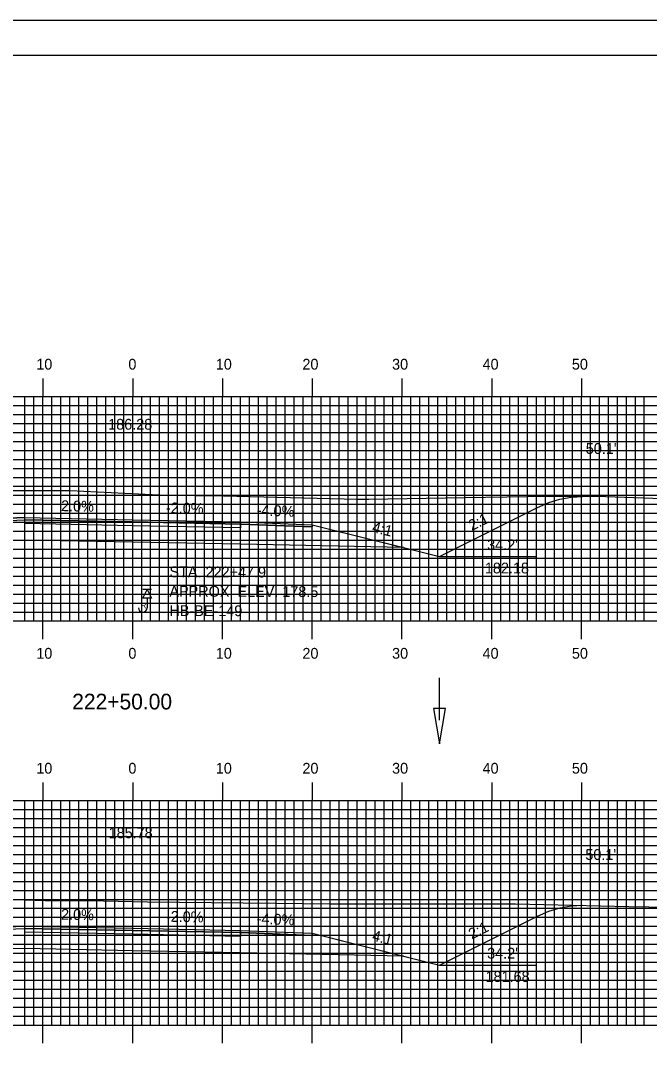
# Model space of a CAD drawing. Extents: x 1797601 to 1797944, y 442591 to 442811.
# Drawn here: x 1797753.9 to 1797824, y 442696.2 to 442810.5 of the extents above; entities that cross this region are included whole.
import ezdxf

# ---------------------------------------------------------------- set-up
doc = ezdxf.new("R2010")
doc.units = 0
for name, color, linetype in [('ANNOTATION', 7, 'Continuous'), ('BORDER', 7, 'Continuous'), ('BORING - REFUSAL', 7, 'Continuous'), ('D_Drainage_Ditch_Line', 7, 'Continuous'), ('D_Roadway_Centerline', 7, 'Continuous'), ('D_Roadway_Centerline_Text', 7, 'Continuous'), ('D_Roadway_Edge_Shoulder', 7, 'Continuous'), ('D_Roadway_Edge_TW', 7, 'Continuous'), ('D_Roadway_Pavement', 7, 'Continuous'), ('D_Roadway_SlopeLines', 7, 'Continuous'), ('D_Roadway_SubGrade', 7, 'Continuous'), ('D_Text_Standard', 7, 'Continuous'), ('H_V ANNOTATION', 7, 'Continuous'), ('MAJOR', 7, 'Continuous'), ('MINOR', 7, 'Continuous'), ('PDRAIN', 7, 'Continuous'), ('PLOT BOUNDARY', 7, 'Continuous'), ('S_Roadway_Centerline', 7, 'Continuous')]:
    doc.layers.add(name, color=color, linetype=linetype)

msp = doc.modelspace()

# ---------------------------------------------------------------- linework, layer by layer
at = {"layer": 'BORDER'}
msp.add_lwpolyline([(1797616.84, 442596.67), (1797936.84, 442596.67), (1797936.84, 442806.67), (1797616.84, 442806.67)], close=True, dxfattribs=at)
at = {"layer": 'BORING - REFUSAL'}
for p, q in [((1797768.52, 442747.17), (1797767.56, 442747.17)), ((1797768.04, 442746.21), (1797768.04, 442745.15))]:
    msp.add_line(p, q, dxfattribs=at)
msp.add_lwpolyline([(1797768.04, 442747.17), (1797768.52, 442746.21), (1797767.56, 442746.21)], close=True, dxfattribs=at)
msp.add_arc((1797767.56, 442745.15), 0.485, 180, 0, dxfattribs=at)
at = {"layer": 'D_Drainage_Ditch_Line'}
msp.add_line((1797800.62, 442732.63), (1797800.62, 442737.33), dxfattribs=at)
msp.add_lwpolyline([(1797801.28, 442733.94), (1797799.96, 442733.94), (1797800.62, 442730)], close=True, dxfattribs=at)
at = {"layer": 'D_Roadway_Centerline'}
for points in [[(1797715.7, 442758.42), (1797716.95, 442758.32), (1797718.2, 442758.06), (1797719.45, 442757.66), (1797720.7, 442757.11), (1797732.27, 442751.33), (1797736.27, 442752.33), (1797746.44, 442754.87), (1797754.44, 442755.19), (1797766.44, 442754.95), (1797778.44, 442754.71), (1797786.44, 442754.39), (1797796.62, 442751.85), (1797800.62, 442750.85), (1797811.54, 442756.31), (1797812.79, 442756.85), (1797814.04, 442757.24), (1797815.29, 442757.48), (1797816.54, 442757.55)], [(1797715.24, 442713.09), (1797716.49, 442713.01), (1797717.74, 442712.78), (1797718.99, 442712.39), (1797720.24, 442711.84), (1797732.27, 442705.83), (1797736.27, 442706.83), (1797746.44, 442709.37), (1797754.44, 442709.69), (1797766.44, 442709.45), (1797778.44, 442709.21), (1797786.44, 442708.89), (1797796.62, 442706.35), (1797800.62, 442705.35), (1797811.55, 442710.81), (1797812.8, 442711.35), (1797814.05, 442711.73), (1797815.3, 442711.95), (1797816.55, 442712.01)]]:
    msp.add_lwpolyline(points, dxfattribs=at)
at = {"layer": 'D_Roadway_Edge_Shoulder'}
for points in [[(1797754.44, 442755.19), (1797746.44, 442754.87), (1797746.44, 442754.62), (1797754.44, 442754.94)], [(1797778.44, 442754.71), (1797786.44, 442754.39), (1797786.44, 442754.14), (1797778.44, 442754.46)], [(1797754.44, 442709.69), (1797746.44, 442709.37), (1797746.44, 442709.12), (1797754.44, 442709.44)], [(1797778.44, 442709.21), (1797786.44, 442708.89), (1797786.44, 442708.64), (1797778.44, 442708.96)]]:
    msp.add_lwpolyline(points, close=True, dxfattribs=at)
at = {"layer": 'D_Roadway_Edge_TW'}
for points in [[(1797754.44, 442754.94), (1797754.44, 442755.19), (1797766.44, 442754.95), (1797778.44, 442754.71), (1797778.44, 442754.46), (1797766.44, 442754.7)], [(1797754.44, 442709.44), (1797754.44, 442709.69), (1797766.44, 442709.45), (1797778.44, 442709.21), (1797778.44, 442708.96), (1797766.44, 442709.2)]]:
    msp.add_lwpolyline(points, close=True, dxfattribs=at)
at = {"layer": 'D_Roadway_Pavement'}
for points in [[(1797754.44, 442754.52), (1797754.44, 442754.94), (1797766.44, 442754.7), (1797778.44, 442754.46), (1797778.44, 442754.04), (1797766.44, 442754.28)], [(1797754.44, 442709.02), (1797754.44, 442709.44), (1797766.44, 442709.2), (1797778.44, 442708.96), (1797778.44, 442708.54), (1797766.44, 442708.78)]]:
    msp.add_lwpolyline(points, close=True, dxfattribs=at)
at = {"layer": 'D_Roadway_SlopeLines'}
for points in [[(1797800.62, 442750.85), (1797811.54, 442756.31), (1797812.79, 442756.85), (1797814.04, 442757.24), (1797815.29, 442757.48), (1797816.54, 442757.55)], [(1797786.44, 442754.39), (1797800.62, 442750.85)], [(1797800.62, 442705.35), (1797811.55, 442710.81), (1797812.8, 442711.35), (1797814.05, 442711.73), (1797815.3, 442711.95), (1797816.55, 442712.01)], [(1797786.44, 442708.89), (1797800.62, 442705.35)]]:
    msp.add_lwpolyline(points, dxfattribs=at)
at = {"layer": 'D_Roadway_SubGrade'}
for points in [[(1797754.44, 442752.69), (1797736.27, 442752.33), (1797746.44, 442754.87), (1797746.44, 442754.62), (1797754.44, 442754.94), (1797766.44, 442754.7), (1797778.44, 442754.46), (1797786.44, 442754.14), (1797786.44, 442754.39), (1797796.62, 442751.85), (1797778.44, 442752.21), (1797766.44, 442752.45)], [(1797754.44, 442707.19), (1797736.27, 442706.83), (1797746.44, 442709.37), (1797746.44, 442709.12), (1797754.44, 442709.44), (1797766.44, 442709.2), (1797778.44, 442708.96), (1797786.44, 442708.64), (1797786.44, 442708.89), (1797796.62, 442706.35), (1797778.44, 442706.71), (1797766.44, 442706.95)]]:
    msp.add_lwpolyline(points, close=True, dxfattribs=at)
at = {"layer": 'MAJOR'}
for p, q in [((1797756.44, 442770.67), (1797756.44, 442768.67)), ((1797766.44, 442770.67), (1797766.44, 442768.67)), ((1797776.44, 442770.67), (1797776.44, 442768.67)), ((1797786.44, 442770.67), (1797786.44, 442768.67)), ((1797796.44, 442770.67), (1797796.44, 442768.67)), ((1797806.44, 442770.67), (1797806.44, 442768.67)), ((1797816.44, 442770.67), (1797816.44, 442768.67)), ((1797626.44, 442768.67), (1797906.44, 442768.67)), ((1797626.44, 442768.67), (1797906.44, 442768.67)), ((1797756.44, 442743.67), (1797756.44, 442768.67)), ((1797766.44, 442743.67), (1797766.44, 442768.67)), ((1797776.44, 442743.67), (1797776.44, 442768.67)), ((1797786.44, 442743.67), (1797786.44, 442768.67)), ((1797796.44, 442743.67), (1797796.44, 442768.67)), ((1797806.44, 442743.67), (1797806.44, 442768.67)), ((1797816.44, 442743.67), (1797816.44, 442768.67)), ((1797626.44, 442763.67), (1797906.44, 442763.67)), ((1797626.44, 442758.67), (1797906.44, 442758.67)), ((1797626.44, 442753.67), (1797906.44, 442753.67)), ((1797626.44, 442748.67), (1797906.44, 442748.67)), ((1797626.44, 442743.67), (1797906.44, 442743.67)), ((1797626.44, 442743.67), (1797906.44, 442743.67)), ((1797756.44, 442741.66), (1797756.44, 442743.67)), ((1797766.44, 442741.66), (1797766.44, 442743.67)), ((1797776.44, 442741.66), (1797776.44, 442743.67)), ((1797786.44, 442741.66), (1797786.44, 442743.67)), ((1797796.44, 442741.66), (1797796.44, 442743.67)), ((1797806.44, 442741.66), (1797806.44, 442743.67)), ((1797816.44, 442741.66), (1797816.44, 442743.67)), ((1797756.44, 442725.67), (1797756.44, 442723.67)), ((1797766.44, 442725.67), (1797766.44, 442723.67)), ((1797776.44, 442725.67), (1797776.44, 442723.67)), ((1797786.44, 442725.67), (1797786.44, 442723.67)), ((1797796.44, 442725.67), (1797796.44, 442723.67)), ((1797806.44, 442725.67), (1797806.44, 442723.67)), ((1797816.44, 442725.67), (1797816.44, 442723.67)), ((1797626.44, 442723.67), (1797906.44, 442723.67)), ((1797626.44, 442723.67), (1797906.44, 442723.67)), ((1797756.44, 442698.67), (1797756.44, 442723.67)), ((1797766.44, 442698.67), (1797766.44, 442723.67)), ((1797776.44, 442698.67), (1797776.44, 442723.67)), ((1797786.44, 442698.67), (1797786.44, 442723.67)), ((1797796.44, 442698.67), (1797796.44, 442723.67)), ((1797806.44, 442698.67), (1797806.44, 442723.67)), ((1797816.44, 442698.67), (1797816.44, 442723.67)), ((1797626.44, 442718.67), (1797906.44, 442718.67)), ((1797626.44, 442713.67), (1797906.44, 442713.67)), ((1797626.44, 442708.67), (1797906.44, 442708.67)), ((1797626.44, 442703.67), (1797906.44, 442703.67)), ((1797626.44, 442698.67), (1797906.44, 442698.67)), ((1797626.44, 442698.67), (1797906.44, 442698.67)), ((1797756.44, 442696.66), (1797756.44, 442698.67)), ((1797766.44, 442696.66), (1797766.44, 442698.67)), ((1797776.44, 442696.66), (1797776.44, 442698.67)), ((1797786.44, 442696.66), (1797786.44, 442698.67)), ((1797796.44, 442696.66), (1797796.44, 442698.67)), ((1797806.44, 442696.66), (1797806.44, 442698.67)), ((1797816.44, 442696.66), (1797816.44, 442698.67))]:
    msp.add_line(p, q, dxfattribs=at)
at = {"layer": 'MINOR'}
for p, q in [((1797626.44, 442767.67), (1797906.44, 442767.67)), ((1797754.44, 442743.67), (1797754.44, 442768.67)), ((1797755.44, 442743.67), (1797755.44, 442768.67)), ((1797757.44, 442743.67), (1797757.44, 442768.67)), ((1797758.44, 442743.67), (1797758.44, 442768.67)), ((1797759.44, 442743.67), (1797759.44, 442768.67)), ((1797760.44, 442743.67), (1797760.44, 442768.67)), ((1797761.44, 442743.67), (1797761.44, 442768.67)), ((1797762.44, 442743.67), (1797762.44, 442768.67)), ((1797763.44, 442743.67), (1797763.44, 442768.67)), ((1797764.44, 442743.67), (1797764.44, 442768.67)), ((1797765.44, 442743.67), (1797765.44, 442768.67)), ((1797767.44, 442743.67), (1797767.44, 442768.67)), ((1797768.44, 442743.67), (1797768.44, 442768.67)), ((1797769.44, 442743.67), (1797769.44, 442768.67)), ((1797770.44, 442743.67), (1797770.44, 442768.67)), ((1797771.44, 442743.67), (1797771.44, 442768.67)), ((1797772.44, 442743.67), (1797772.44, 442768.67)), ((1797773.44, 442743.67), (1797773.44, 442768.67)), ((1797774.44, 442743.67), (1797774.44, 442768.67)), ((1797775.44, 442743.67), (1797775.44, 442768.67)), ((1797777.44, 442743.67), (1797777.44, 442768.67)), ((1797778.44, 442743.67), (1797778.44, 442768.67)), ((1797779.44, 442743.67), (1797779.44, 442768.67)), ((1797780.44, 442743.67), (1797780.44, 442768.67)), ((1797781.44, 442743.67), (1797781.44, 442768.67)), ((1797782.44, 442743.67), (1797782.44, 442768.67)), ((1797783.44, 442743.67), (1797783.44, 442768.67)), ((1797784.44, 442743.67), (1797784.44, 442768.67)), ((1797785.44, 442743.67), (1797785.44, 442768.67)), ((1797787.44, 442743.67), (1797787.44, 442768.67)), ((1797788.44, 442743.67), (1797788.44, 442768.67)), ((1797789.44, 442743.67), (1797789.44, 442768.67)), ((1797790.44, 442743.67), (1797790.44, 442768.67)), ((1797791.44, 442743.67), (1797791.44, 442768.67)), ((1797792.44, 442743.67), (1797792.44, 442768.67)), ((1797793.44, 442743.67), (1797793.44, 442768.67)), ((1797794.44, 442743.67), (1797794.44, 442768.67)), ((1797795.44, 442743.67), (1797795.44, 442768.67)), ((1797797.44, 442743.67), (1797797.44, 442768.67)), ((1797798.44, 442743.67), (1797798.44, 442768.67)), ((1797799.44, 442743.67), (1797799.44, 442768.67)), ((1797800.44, 442743.67), (1797800.44, 442768.67)), ((1797801.44, 442743.67), (1797801.44, 442768.67)), ((1797802.44, 442743.67), (1797802.44, 442768.67)), ((1797803.44, 442743.67), (1797803.44, 442768.67)), ((1797804.44, 442743.67), (1797804.44, 442768.67)), ((1797805.44, 442743.67), (1797805.44, 442768.67)), ((1797807.44, 442743.67), (1797807.44, 442768.67)), ((1797808.44, 442743.67), (1797808.44, 442768.67)), ((1797809.44, 442743.67), (1797809.44, 442768.67)), ((1797810.44, 442743.67), (1797810.44, 442768.67)), ((1797811.44, 442743.67), (1797811.44, 442768.67)), ((1797812.44, 442743.67), (1797812.44, 442768.67)), ((1797813.44, 442743.67), (1797813.44, 442768.67)), ((1797814.44, 442743.67), (1797814.44, 442768.67)), ((1797815.44, 442743.67), (1797815.44, 442768.67)), ((1797817.44, 442743.67), (1797817.44, 442768.67)), ((1797818.44, 442743.67), (1797818.44, 442768.67)), ((1797819.44, 442743.67), (1797819.44, 442768.67)), ((1797820.44, 442743.67), (1797820.44, 442768.67)), ((1797821.44, 442743.67), (1797821.44, 442768.67)), ((1797822.44, 442743.67), (1797822.44, 442768.67)), ((1797823.44, 442743.67), (1797823.44, 442768.67)), ((1797626.44, 442766.67), (1797906.44, 442766.67)), ((1797626.44, 442765.67), (1797906.44, 442765.67)), ((1797626.44, 442764.67), (1797906.44, 442764.67)), ((1797626.44, 442762.67), (1797906.44, 442762.67)), ((1797626.44, 442761.67), (1797906.44, 442761.67)), ((1797626.44, 442760.67), (1797906.44, 442760.67)), ((1797626.44, 442759.67), (1797906.44, 442759.67)), ((1797626.44, 442757.67), (1797906.44, 442757.67)), ((1797626.44, 442756.67), (1797906.44, 442756.67)), ((1797626.44, 442755.67), (1797906.44, 442755.67)), ((1797626.44, 442754.67), (1797906.44, 442754.67)), ((1797626.44, 442752.67), (1797906.44, 442752.67)), ((1797626.44, 442751.67), (1797906.44, 442751.67)), ((1797626.44, 442750.67), (1797906.44, 442750.67)), ((1797626.44, 442749.67), (1797906.44, 442749.67)), ((1797626.44, 442747.67), (1797906.44, 442747.67)), ((1797626.44, 442746.67), (1797906.44, 442746.67)), ((1797626.44, 442745.67), (1797906.44, 442745.67)), ((1797626.44, 442744.67), (1797906.44, 442744.67)), ((1797754.44, 442698.67), (1797754.44, 442723.67)), ((1797755.44, 442698.67), (1797755.44, 442723.67)), ((1797757.44, 442698.67), (1797757.44, 442723.67)), ((1797758.44, 442698.67), (1797758.44, 442723.67)), ((1797759.44, 442698.67), (1797759.44, 442723.67)), ((1797760.44, 442698.67), (1797760.44, 442723.67)), ((1797761.44, 442698.67), (1797761.44, 442723.67)), ((1797762.44, 442698.67), (1797762.44, 442723.67)), ((1797763.44, 442698.67), (1797763.44, 442723.67)), ((1797764.44, 442698.67), (1797764.44, 442723.67)), ((1797765.44, 442698.67), (1797765.44, 442723.67)), ((1797767.44, 442698.67), (1797767.44, 442723.67)), ((1797768.44, 442698.67), (1797768.44, 442723.67)), ((1797769.44, 442698.67), (1797769.44, 442723.67)), ((1797770.44, 442698.67), (1797770.44, 442723.67)), ((1797771.44, 442698.67), (1797771.44, 442723.67)), ((1797772.44, 442698.67), (1797772.44, 442723.67)), ((1797773.44, 442698.67), (1797773.44, 442723.67)), ((1797774.44, 442698.67), (1797774.44, 442723.67)), ((1797775.44, 442698.67), (1797775.44, 442723.67)), ((1797777.44, 442698.67), (1797777.44, 442723.67)), ((1797778.44, 442698.67), (1797778.44, 442723.67)), ((1797779.44, 442698.67), (1797779.44, 442723.67)), ((1797780.44, 442698.67), (1797780.44, 442723.67)), ((1797781.44, 442698.67), (1797781.44, 442723.67)), ((1797782.44, 442698.67), (1797782.44, 442723.67)), ((1797783.44, 442698.67), (1797783.44, 442723.67)), ((1797784.44, 442698.67), (1797784.44, 442723.67)), ((1797785.44, 442698.67), (1797785.44, 442723.67)), ((1797787.44, 442698.67), (1797787.44, 442723.67)), ((1797788.44, 442698.67), (1797788.44, 442723.67)), ((1797789.44, 442698.67), (1797789.44, 442723.67)), ((1797790.44, 442698.67), (1797790.44, 442723.67)), ((1797791.44, 442698.67), (1797791.44, 442723.67)), ((1797792.44, 442698.67), (1797792.44, 442723.67)), ((1797793.44, 442698.67), (1797793.44, 442723.67)), ((1797794.44, 442698.67), (1797794.44, 442723.67)), ((1797795.44, 442698.67), (1797795.44, 442723.67)), ((1797797.44, 442698.67), (1797797.44, 442723.67)), ((1797798.44, 442698.67), (1797798.44, 442723.67)), ((1797799.44, 442698.67), (1797799.44, 442723.67)), ((1797800.44, 442698.67), (1797800.44, 442723.67)), ((1797801.44, 442698.67), (1797801.44, 442723.67)), ((1797802.44, 442698.67), (1797802.44, 442723.67)), ((1797803.44, 442698.67), (1797803.44, 442723.67)), ((1797804.44, 442698.67), (1797804.44, 442723.67)), ((1797805.44, 442698.67), (1797805.44, 442723.67)), ((1797807.44, 442698.67), (1797807.44, 442723.67)), ((1797808.44, 442698.67), (1797808.44, 442723.67)), ((1797809.44, 442698.67), (1797809.44, 442723.67)), ((1797810.44, 442698.67), (1797810.44, 442723.67)), ((1797811.44, 442698.67), (1797811.44, 442723.67)), ((1797812.44, 442698.67), (1797812.44, 442723.67)), ((1797813.44, 442698.67), (1797813.44, 442723.67)), ((1797814.44, 442698.67), (1797814.44, 442723.67)), ((1797815.44, 442698.67), (1797815.44, 442723.67)), ((1797817.44, 442698.67), (1797817.44, 442723.67)), ((1797818.44, 442698.67), (1797818.44, 442723.67)), ((1797819.44, 442698.67), (1797819.44, 442723.67)), ((1797820.44, 442698.67), (1797820.44, 442723.67)), ((1797821.44, 442698.67), (1797821.44, 442723.67)), ((1797822.44, 442698.67), (1797822.44, 442723.67)), ((1797823.44, 442698.67), (1797823.44, 442723.67)), ((1797626.44, 442722.67), (1797906.44, 442722.67)), ((1797626.44, 442721.67), (1797906.44, 442721.67)), ((1797626.44, 442720.67), (1797906.44, 442720.67)), ((1797626.44, 442719.67), (1797906.44, 442719.67)), ((1797626.44, 442717.67), (1797906.44, 442717.67)), ((1797626.44, 442716.67), (1797906.44, 442716.67)), ((1797626.44, 442715.67), (1797906.44, 442715.67)), ((1797626.44, 442714.67), (1797906.44, 442714.67)), ((1797626.44, 442712.67), (1797906.44, 442712.67)), ((1797626.44, 442711.67), (1797906.44, 442711.67)), ((1797626.44, 442710.67), (1797906.44, 442710.67)), ((1797626.44, 442709.67), (1797906.44, 442709.67)), ((1797626.44, 442707.67), (1797906.44, 442707.67)), ((1797626.44, 442706.67), (1797906.44, 442706.67)), ((1797626.44, 442705.67), (1797906.44, 442705.67)), ((1797626.44, 442704.67), (1797906.44, 442704.67)), ((1797626.44, 442702.67), (1797906.44, 442702.67)), ((1797626.44, 442701.67), (1797906.44, 442701.67)), ((1797626.44, 442700.67), (1797906.44, 442700.67)), ((1797626.44, 442699.67), (1797906.44, 442699.67))]:
    msp.add_line(p, q, dxfattribs=at)
at = {"layer": 'PDRAIN'}
for p, q in [((1797800.62, 442750.85), (1797811.39, 442750.85)), ((1797800.62, 442705.35), (1797811.39, 442705.35))]:
    msp.add_line(p, q, dxfattribs=at)
at = {"layer": 'PLOT BOUNDARY'}
msp.add_lwpolyline([(1797600.66, 442590.55), (1797940.66, 442590.55), (1797940.66, 442810.55), (1797600.66, 442810.55)], close=True, dxfattribs=at)
at = {"layer": 'S_Roadway_Centerline'}
for points in [[(1797687.49, 442758.66), (1797706.84, 442758.62), (1797714.27, 442758.46), (1797719.49, 442758.33), (1797727.64, 442757.98), (1797739.12, 442757.93), (1797748.29, 442758.14), (1797750.47, 442758.21), (1797759.46, 442758.19), (1797770.12, 442757.67), (1797776.56, 442757.62), (1797791.48, 442757.23), (1797792.06, 442757.23), (1797792.74, 442757.24), (1797803.41, 442757.41), (1797812.83, 442757.56), (1797815.62, 442757.56), (1797819.14, 442757.53), (1797826.47, 442757.28)], [(1797684.96, 442713.57), (1797703.19, 442713.25), (1797706.24, 442713.08), (1797717.85, 442713.09), (1797726.83, 442713.11), (1797728.09, 442713.12), (1797729.92, 442713.04), (1797739.67, 442712.73), (1797747.14, 442712.67), (1797751.16, 442712.71), (1797756.7, 442712.55), (1797763.19, 442712.49), (1797768.08, 442712.38), (1797782.33, 442712.24), (1797788.49, 442712.18), (1797807.51, 442712.17), (1797808.37, 442712.16), (1797809.09, 442712.17), (1797821.72, 442711.89), (1797830.65, 442711.71)]]:
    msp.add_lwpolyline(points, dxfattribs=at)

# ---------------------------------------------------------------- texts
at = {"layer": 'ANNOTATION'}
for s, rotation, p in [('2.0%', 358.8542, (1797758.45, 442755.91)), ('-2.0%', 358.8542, (1797770.13, 442755.68)), ('-4.0%', 357.7094, (1797780.24, 442755.44)), ('2:1', 26.5651, (1797804.23, 442753.69)), ('4:1', 345.9638, (1797793.04, 442753.6)), ('2.0%', 358.8542, (1797758.45, 442710.41)), ('-2.0%', 358.8542, (1797770.13, 442710.18)), ('-4.0%', 357.7094, (1797780.24, 442709.94)), ('2:1', 26.5651, (1797804.23, 442708.19)), ('4:1', 345.9638, (1797793.04, 442708.1))]:
    msp.add_text(s, height=1.2, rotation=rotation, dxfattribs=at).set_placement(p)
for s, p in [("34.2'", (1797805.93, 442751.57)), ('182.18', (1797805.68, 442748.97)), ("34.2'", (1797805.93, 442706.07)), ('181.68', (1797805.75, 442703.47))]:
    msp.add_text(s, height=1.2, dxfattribs=at).set_placement(p)
at = {"layer": 'BORING - REFUSAL'}
for s, p in [('STA. 222+47.9', (1797770.54, 442748.55)), ('APPROX. ELEV. 178.5', (1797770.53, 442746.39)), ('HB-BE-149', (1797770.53, 442744.23))]:
    msp.add_text(s, height=1.2, rotation=359.8142, dxfattribs=at).set_placement(p)
msp.add_text('R', height=0.64, dxfattribs=at).set_placement((1797767.34, 442745.09))
at = {"layer": 'D_Roadway_Centerline'}
for s, p in [('C', (1797766.44, 442754.95)), ('L', (1797766.44, 442754.94)), ('C', (1797766.44, 442709.45)), ('L', (1797766.44, 442709.44))]:
    msp.add_text(s, height=0.0146, dxfattribs=at).set_placement(p)
at = {"layer": 'D_Roadway_Centerline_Text'}
for s, p in [('186.28', (1797763.71, 442764.98)), ('185.78', (1797763.76, 442719.48))]:
    msp.add_text(s, height=1.2, dxfattribs=at).set_placement(p)
at = {"layer": 'D_Text_Standard'}
for p in [(1797816.92, 442762.28), (1797816.87, 442717.06)]:
    msp.add_text("50.1'", height=1.2, dxfattribs=at).set_placement(p)
at = {"layer": 'H_V ANNOTATION'}
for s, height, p in [('10', 1.2, (1797755.7, 442771.67)), ('0', 1.2, (1797765.96, 442771.67)), ('10', 1.2, (1797775.7, 442771.67)), ('20', 1.2, (1797785.35, 442771.67)), ('30', 1.2, (1797795.34, 442771.67)), ('40', 1.2, (1797805.42, 442771.67)), ('50', 1.2, (1797815.37, 442771.67)), ('10', 1.2, (1797755.7, 442739.47)), ('0', 1.2, (1797765.96, 442739.47)), ('10', 1.2, (1797775.7, 442739.47)), ('20', 1.2, (1797785.35, 442739.47)), ('30', 1.2, (1797795.34, 442739.47)), ('40', 1.2, (1797805.42, 442739.47)), ('50', 1.2, (1797815.37, 442739.47)), ('222+50.00', 1.75, (1797759.7, 442733.82)), ('10', 1.2, (1797755.7, 442726.67)), ('0', 1.2, (1797765.96, 442726.67)), ('10', 1.2, (1797775.7, 442726.67)), ('20', 1.2, (1797785.35, 442726.67)), ('30', 1.2, (1797795.34, 442726.67)), ('40', 1.2, (1797805.42, 442726.67)), ('50', 1.2, (1797815.37, 442726.67))]:
    msp.add_text(s, height=height, dxfattribs=at).set_placement(p)

doc.saveas('drawing.dxf')
